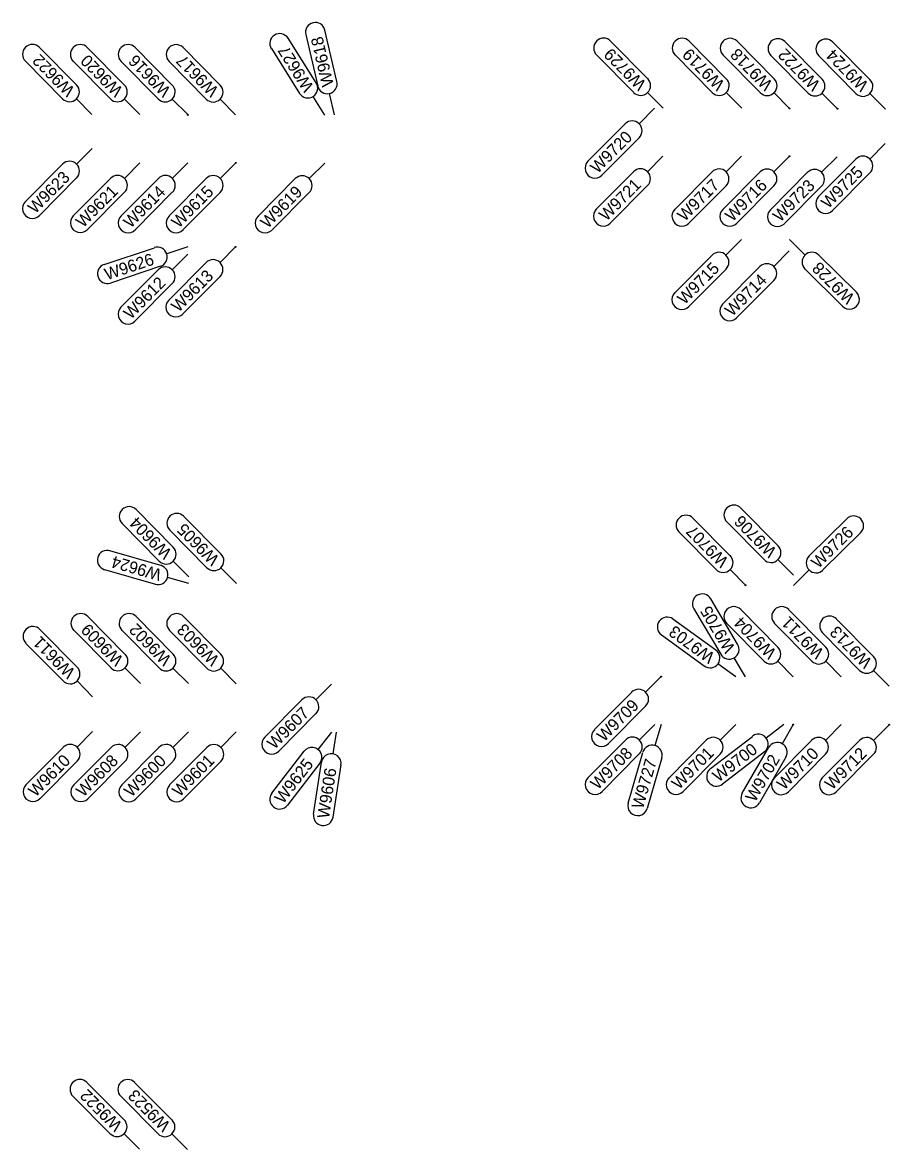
# Model space of a CAD drawing. Extents: x 12479652 to 12487250, y 9842710 to 9846560.
# Drawn here: x 12483660.6 to 12483751.2, y 9844494.3 to 9844612 of the extents above; entities that cross this region are included whole.
import ezdxf

# ---------------------------------------------------------------- set-up
doc = ezdxf.new("R2010")
doc.units = 0
doc.layers.add('Default', color=7, linetype='Continuous')
doc.layers.add('TextAlignmentLrg', color=7, linetype='Continuous')

msp = doc.modelspace()

# ---------------------------------------------------------------- linework, layer by layer
at = {"layer": 'Default'}
for p, q in [((12483690.21, 9844610.71), (12483691.46, 9844605.34)), ((12483693.46, 9844605.8), (12483692.21, 9844611.17)), ((12483691.3, 9844605.66), (12483688.36, 9844610.33)), ((12483725.91, 9844606.11), (12483722.04, 9844610.03)), ((12483734.12, 9844606.1), (12483730.24, 9844610.02)), ((12483739.12, 9844606.09), (12483735.24, 9844610.02)), ((12483744.12, 9844606.05), (12483740.24, 9844609.97)), ((12483749.12, 9844606.01), (12483745.24, 9844609.93)), ((12483666.28, 9844605.45), (12483662.4, 9844609.37)), ((12483671.28, 9844605.44), (12483667.4, 9844609.36)), ((12483676.28, 9844605.43), (12483672.4, 9844609.36)), ((12483681.28, 9844605.42), (12483677.4, 9844609.35)), ((12483686.62, 9844609.24), (12483689.56, 9844604.57)), ((12483720.58, 9844608.59), (12483724.45, 9844604.67)), ((12483728.78, 9844608.58), (12483732.66, 9844604.66)), ((12483733.78, 9844608.57), (12483737.66, 9844604.65)), ((12483738.78, 9844608.53), (12483742.66, 9844604.61)), ((12483743.78, 9844608.49), (12483747.66, 9844604.57)), ((12483660.94, 9844607.93), (12483664.82, 9844604.01)), ((12483665.94, 9844607.92), (12483669.82, 9844604)), ((12483670.94, 9844607.91), (12483674.82, 9844603.99)), ((12483675.94, 9844607.91), (12483679.82, 9844603.98)), ((12483667.89, 9844602.36), (12483666.27, 9844604)), ((12483672.89, 9844602.35), (12483671.27, 9844603.99)), ((12483677.89, 9844602.35), (12483676.27, 9844603.98)), ((12483682.89, 9844602.34), (12483681.27, 9844603.97)), ((12483692.2, 9844602.3), (12483690.97, 9844604.25)), ((12483693.22, 9844602.33), (12483692.7, 9844604.57)), ((12483727.52, 9844603.02), (12483725.91, 9844604.66)), ((12483735.73, 9844603.01), (12483734.11, 9844604.65)), ((12483740.73, 9844603), (12483739.11, 9844604.64)), ((12483745.73, 9844602.96), (12483744.11, 9844604.6)), ((12483750.73, 9844602.92), (12483749.11, 9844604.56)), ((12483726.63, 9844603.03), (12483725.01, 9844601.39)), ((12483719.67, 9844597.48), (12483723.56, 9844601.39)), ((12483725.02, 9844599.94), (12483721.13, 9844596.03)), ((12483750.72, 9844599.35), (12483749.1, 9844597.71)), ((12483667.9, 9844598.82), (12483666.28, 9844597.19)), ((12483727.51, 9844598.02), (12483725.89, 9844596.39)), ((12483735.72, 9844598.01), (12483734.1, 9844596.38)), ((12483740.72, 9844598), (12483739.1, 9844596.37)), ((12483743.76, 9844593.8), (12483747.65, 9844597.71)), ((12483745.69, 9844597.96), (12483744.06, 9844596.33)), ((12483660.94, 9844593.27), (12483664.83, 9844597.18)), ((12483672.9, 9844597.33), (12483671.28, 9844595.7)), ((12483677.9, 9844597.32), (12483676.28, 9844595.69)), ((12483682.9, 9844597.32), (12483681.28, 9844595.69)), ((12483692.19, 9844597.3), (12483690.57, 9844595.67)), ((12483666.29, 9844595.74), (12483662.4, 9844591.82)), ((12483665.94, 9844591.78), (12483669.83, 9844595.7)), ((12483670.94, 9844591.78), (12483674.83, 9844595.69)), ((12483675.94, 9844591.77), (12483679.83, 9844595.68)), ((12483685.23, 9844591.75), (12483689.12, 9844595.67)), ((12483720.55, 9844592.48), (12483724.44, 9844596.39)), ((12483728.76, 9844592.46), (12483732.65, 9844596.38)), ((12483733.76, 9844592.46), (12483737.65, 9844596.37)), ((12483738.72, 9844592.42), (12483742.61, 9844596.33)), ((12483749.1, 9844596.26), (12483745.21, 9844592.35)), ((12483671.28, 9844594.25), (12483667.39, 9844590.34)), ((12483676.28, 9844594.24), (12483672.39, 9844590.33)), ((12483681.28, 9844594.23), (12483677.39, 9844590.32)), ((12483690.58, 9844594.22), (12483686.69, 9844590.31)), ((12483725.9, 9844594.94), (12483722.01, 9844591.03)), ((12483734.1, 9844594.93), (12483730.21, 9844591.02)), ((12483739.1, 9844594.92), (12483735.21, 9844591.01)), ((12483744.07, 9844594.88), (12483740.18, 9844590.97)), ((12483669.18, 9844586.71), (12483674.41, 9844588.46)), ((12483677.89, 9844588.54), (12483675.71, 9844587.81)), ((12483682.89, 9844588.54), (12483681.27, 9844586.9)), ((12483735.71, 9844589.31), (12483734.08, 9844587.68)), ((12483740.71, 9844589.31), (12483742.34, 9844587.68)), ((12483677.89, 9844587.79), (12483676.27, 9844586.16)), ((12483728.74, 9844583.76), (12483732.63, 9844587.68)), ((12483740.7, 9844588.12), (12483739.08, 9844586.49)), ((12483743.79, 9844587.69), (12483747.7, 9844583.8)), ((12483675.06, 9844586.52), (12483669.83, 9844584.77)), ((12483670.92, 9844582.24), (12483674.81, 9844586.16)), ((12483675.93, 9844582.99), (12483679.82, 9844586.9)), ((12483734.09, 9844586.23), (12483730.2, 9844582.32)), ((12483733.74, 9844582.57), (12483737.63, 9844586.49)), ((12483746.25, 9844582.34), (12483742.34, 9844586.23)), ((12483681.27, 9844585.45), (12483677.38, 9844581.54)), ((12483739.09, 9844585.04), (12483735.2, 9844581.13)), ((12483676.27, 9844584.71), (12483672.38, 9844580.8)), ((12483739.52, 9844557.34), (12483735.64, 9844561.27)), ((12483676.38, 9844557.18), (12483672.5, 9844561.11)), ((12483681.36, 9844556.49), (12483677.48, 9844560.41)), ((12483734.52, 9844556.3), (12483730.64, 9844560.22)), ((12483746.7, 9844560.15), (12483742.77, 9844556.27)), ((12483671.04, 9844559.67), (12483674.92, 9844555.74)), ((12483676.02, 9844558.97), (12483679.9, 9844555.04)), ((12483734.18, 9844559.83), (12483738.06, 9844555.9)), ((12483729.18, 9844558.78), (12483733.06, 9844554.86)), ((12483744.21, 9844554.81), (12483748.14, 9844558.69)), ((12483675.07, 9844555.29), (12483669.77, 9844556.82)), ((12483677.99, 9844554.1), (12483676.37, 9844555.73)), ((12483741.13, 9844554.26), (12483739.51, 9844555.89)), ((12483669.21, 9844554.85), (12483674.51, 9844553.32)), ((12483682.97, 9844553.4), (12483681.35, 9844555.04)), ((12483736.13, 9844553.21), (12483734.51, 9844554.85)), ((12483741.13, 9844553.2), (12483742.76, 9844554.82)), ((12483677.99, 9844553.39), (12483675.78, 9844554.02)), ((12483735.3, 9844547.06), (12483732.5, 9844551.81)), ((12483730.73, 9844550.76), (12483733.54, 9844546.01)), ((12483739.51, 9844546.75), (12483735.63, 9844550.67)), ((12483744.51, 9844546.74), (12483740.63, 9844550.67)), ((12483671.34, 9844546.03), (12483667.46, 9844549.95)), ((12483676.36, 9844546.02), (12483672.49, 9844549.95)), ((12483681.34, 9844546.01), (12483677.46, 9844549.94)), ((12483733.02, 9844546.45), (12483728.55, 9844549.69)), ((12483749.5, 9844545.77), (12483745.63, 9844549.69)), ((12483666.34, 9844544.67), (12483662.46, 9844548.6)), ((12483666, 9844548.51), (12483669.88, 9844544.59)), ((12483671.03, 9844548.5), (12483674.9, 9844544.58)), ((12483676, 9844548.5), (12483679.88, 9844544.57)), ((12483734.17, 9844549.23), (12483738.05, 9844545.31)), ((12483739.17, 9844549.22), (12483743.05, 9844545.3)), ((12483661, 9844547.15), (12483664.88, 9844543.23)), ((12483727.35, 9844548.03), (12483731.82, 9844544.79)), ((12483744.17, 9844548.25), (12483748.04, 9844544.33)), ((12483735.11, 9844543.67), (12483733.25, 9844545.02)), ((12483736.11, 9844543.67), (12483734.94, 9844545.65)), ((12483741.11, 9844543.66), (12483739.5, 9844545.3)), ((12483746.11, 9844543.66), (12483744.5, 9844545.29)), ((12483672.95, 9844542.94), (12483671.33, 9844544.58)), ((12483677.97, 9844542.94), (12483676.35, 9844544.57)), ((12483682.95, 9844542.93), (12483681.33, 9844544.56)), ((12483727.32, 9844543.68), (12483725.7, 9844542.05)), ((12483751.11, 9844542.68), (12483749.49, 9844544.32)), ((12483667.95, 9844541.58), (12483666.33, 9844543.22)), ((12483692.9, 9844542.89), (12483691.27, 9844541.26)), ((12483685.93, 9844537.34), (12483689.82, 9844541.26)), ((12483720.36, 9844538.14), (12483724.25, 9844542.05)), ((12483725.7, 9844540.6), (12483721.81, 9844536.69)), ((12483691.28, 9844539.81), (12483687.39, 9844535.9)), ((12483667.96, 9844537.93), (12483666.34, 9844536.3)), ((12483672.96, 9844537.92), (12483671.34, 9844536.29)), ((12483677.96, 9844537.91), (12483676.34, 9844536.28)), ((12483682.96, 9844537.91), (12483681.34, 9844536.28)), ((12483692.89, 9844537.89), (12483691.48, 9844536.07)), ((12483693.38, 9844537.89), (12483693.03, 9844535.62)), ((12483726.65, 9844538.68), (12483725.03, 9844537.05)), ((12483727.31, 9844538.68), (12483726.67, 9844536.47)), ((12483735.11, 9844538.67), (12483733.48, 9844537.04)), ((12483740.11, 9844538.66), (12483738.28, 9844537.26)), ((12483741.11, 9844538.66), (12483739.95, 9844536.67)), ((12483746.11, 9844538.66), (12483744.48, 9844537.02)), ((12483751.11, 9844538.65), (12483749.48, 9844537.02)), ((12483719.69, 9844533.14), (12483723.58, 9844537.05)), ((12483728.14, 9844533.12), (12483732.03, 9844537.04)), ((12483732.48, 9844534.07), (12483736.85, 9844537.44)), ((12483739.14, 9844533.11), (12483743.03, 9844537.02)), ((12483744.14, 9844533.1), (12483748.03, 9844537.01)), ((12483661, 9844532.38), (12483664.89, 9844536.29)), ((12483666, 9844532.37), (12483669.89, 9844536.29)), ((12483671, 9844532.37), (12483674.89, 9844536.28)), ((12483676, 9844532.36), (12483679.89, 9844536.27)), ((12483686.68, 9844531.51), (12483690.05, 9844535.88)), ((12483725.04, 9844535.6), (12483721.15, 9844531.69)), ((12483723.88, 9844530.47), (12483725.4, 9844535.77)), ((12483733.49, 9844535.59), (12483729.6, 9844531.68)), ((12483738.1, 9844535.82), (12483733.73, 9844532.45)), ((12483735.79, 9844531.52), (12483738.55, 9844536.3)), ((12483744.49, 9844535.57), (12483740.6, 9844531.66)), ((12483749.49, 9844535.57), (12483745.6, 9844531.65)), ((12483666.35, 9844534.85), (12483662.46, 9844530.93)), ((12483671.35, 9844534.84), (12483667.46, 9844530.93)), ((12483676.35, 9844534.83), (12483672.46, 9844530.92)), ((12483681.35, 9844534.82), (12483677.46, 9844530.91)), ((12483691.67, 9844534.63), (12483688.31, 9844530.26)), ((12483691.02, 9844529.31), (12483691.86, 9844534.76)), ((12483693.89, 9844534.45), (12483693.05, 9844528.99)), ((12483727.38, 9844535.2), (12483725.85, 9844529.9)), ((12483740.33, 9844535.27), (12483737.57, 9844530.49)), ((12483671.24, 9844497.4), (12483667.35, 9844501.31)), ((12483676.24, 9844497.39), (12483672.35, 9844501.3)), ((12483665.9, 9844499.87), (12483669.79, 9844495.95)), ((12483670.9, 9844499.86), (12483674.79, 9844495.94)), ((12483672.86, 9844494.32), (12483671.24, 9844495.95)), ((12483677.86, 9844494.31), (12483676.24, 9844495.94))]:
    msp.add_line(p, q, dxfattribs=at)
for centre, start, end in [((12483691.21, 9844610.94), 13.1464, 193.1464), ((12483687.49, 9844609.78), 32.2035, 212.2035), ((12483661.67, 9844608.65), 44.6553, 224.6553), ((12483666.67, 9844608.64), 44.6553, 224.6553), ((12483671.67, 9844608.64), 44.6553, 224.6553), ((12483676.67, 9844608.63), 44.6553, 224.6553), ((12483721.31, 9844609.31), 44.6553, 224.6553), ((12483729.51, 9844609.3), 44.6553, 224.6553), ((12483734.51, 9844609.29), 44.6553, 224.6553), ((12483739.51, 9844609.25), 44.6553, 224.6553), ((12483744.51, 9844609.21), 44.6553, 224.6553), ((12483725.18, 9844605.39), 224.6553, 44.6553), ((12483733.39, 9844605.38), 224.6553, 44.6553), ((12483738.39, 9844605.37), 224.6553, 44.6553), ((12483743.39, 9844605.33), 224.6553, 44.6553), ((12483748.39, 9844605.29), 224.6553, 44.6553), ((12483665.55, 9844604.73), 224.6553, 44.6553), ((12483670.55, 9844604.72), 224.6553, 44.6553), ((12483675.55, 9844604.71), 224.6553, 44.6553), ((12483680.55, 9844604.7), 224.6553, 44.6553), ((12483690.43, 9844605.12), 212.2035, 32.2035), ((12483692.46, 9844605.57), 193.1464, 13.1464), ((12483724.29, 9844600.67), 315.1702, 135.1702), ((12483748.38, 9844596.99), 315.1702, 135.1702), ((12483665.56, 9844596.46), 315.1702, 135.1702), ((12483720.4, 9844596.75), 135.1702, 315.1702), ((12483725.17, 9844595.67), 315.1702, 135.1702), ((12483733.37, 9844595.65), 315.1702, 135.1702), ((12483738.37, 9844595.64), 315.1702, 135.1702), ((12483743.34, 9844595.6), 315.1702, 135.1702), ((12483670.56, 9844594.97), 315.1702, 135.1702), ((12483675.56, 9844594.97), 315.1702, 135.1702), ((12483680.56, 9844594.96), 315.1702, 135.1702), ((12483689.85, 9844594.94), 315.1702, 135.1702), ((12483661.67, 9844592.55), 135.1702, 315.1702), ((12483744.49, 9844593.07), 135.1702, 315.1702), ((12483721.28, 9844591.75), 135.1702, 315.1702), ((12483729.48, 9844591.74), 135.1702, 315.1702), ((12483734.48, 9844591.73), 135.1702, 315.1702), ((12483739.45, 9844591.69), 135.1702, 315.1702), ((12483666.67, 9844591.06), 135.1702, 315.1702), ((12483671.67, 9844591.05), 135.1702, 315.1702), ((12483676.67, 9844591.04), 135.1702, 315.1702), ((12483685.96, 9844591.03), 135.1702, 315.1702), ((12483674.73, 9844587.49), 288.4892, 108.4892), ((12483680.54, 9844586.18), 315.1702, 135.1702), ((12483733.36, 9844586.95), 315.1702, 135.1702), ((12483743.06, 9844586.96), 45.1702, 225.1702), ((12483669.5, 9844585.74), 108.4892, 288.4892), ((12483675.54, 9844585.43), 315.1702, 135.1702), ((12483738.36, 9844585.76), 315.1702, 135.1702), ((12483729.47, 9844583.04), 135.1702, 315.1702), ((12483746.98, 9844583.07), 225.1702, 45.1702), ((12483676.65, 9844582.26), 135.1702, 315.1702), ((12483734.47, 9844581.85), 135.1702, 315.1702), ((12483671.65, 9844581.52), 135.1702, 315.1702), ((12483671.77, 9844560.39), 44.6553, 224.6553), ((12483734.91, 9844560.55), 44.6553, 224.6553), ((12483676.75, 9844559.69), 44.6553, 224.6553), ((12483729.91, 9844559.5), 44.6553, 224.6553), ((12483747.42, 9844559.42), 314.6553, 134.6553), ((12483669.49, 9844555.83), 73.9221, 253.9221), ((12483675.65, 9844556.46), 224.6553, 44.6553), ((12483738.79, 9844556.62), 224.6553, 44.6553), ((12483680.63, 9844555.77), 224.6553, 44.6553), ((12483733.79, 9844555.58), 224.6553, 44.6553), ((12483743.49, 9844555.54), 134.6553, 314.6553), ((12483674.79, 9844554.31), 253.9221, 73.9221), ((12483731.61, 9844551.28), 30.5813, 210.5813), ((12483734.9, 9844549.95), 44.6553, 224.6553), ((12483739.9, 9844549.95), 44.6553, 224.6553), ((12483666.73, 9844549.23), 44.6553, 224.6553), ((12483671.76, 9844549.23), 44.6553, 224.6553), ((12483676.73, 9844549.22), 44.6553, 224.6553), ((12483727.95, 9844548.86), 54.1073, 234.1073), ((12483744.9, 9844548.97), 44.6553, 224.6553), ((12483661.73, 9844547.88), 44.6553, 224.6553), ((12483670.61, 9844545.31), 224.6553, 44.6553), ((12483675.63, 9844545.3), 224.6553, 44.6553), ((12483680.61, 9844545.29), 224.6553, 44.6553), ((12483732.42, 9844545.62), 234.1073, 54.1073), ((12483734.42, 9844546.53), 210.5813, 30.5813), ((12483738.78, 9844546.03), 224.6553, 44.6553), ((12483743.78, 9844546.02), 224.6553, 44.6553), ((12483748.77, 9844545.05), 224.6553, 44.6553), ((12483665.61, 9844543.95), 224.6553, 44.6553), ((12483690.55, 9844540.53), 315.1702, 135.1702), ((12483724.97, 9844541.32), 315.1702, 135.1702), ((12483721.09, 9844537.41), 135.1702, 315.1702), ((12483665.62, 9844535.57), 315.1702, 135.1702), ((12483670.62, 9844535.56), 315.1702, 135.1702), ((12483675.62, 9844535.56), 315.1702, 135.1702), ((12483680.62, 9844535.55), 315.1702, 135.1702), ((12483686.66, 9844536.62), 135.1702, 315.1702), ((12483724.31, 9844536.33), 315.1702, 135.1702), ((12483726.39, 9844535.49), 343.9089, 163.9089), ((12483732.76, 9844536.31), 315.1702, 135.1702), ((12483737.47, 9844536.63), 307.657, 127.657), ((12483739.44, 9844535.78), 329.9638, 149.9638), ((12483743.76, 9844536.3), 315.1702, 135.1702), ((12483748.76, 9844536.29), 315.1702, 135.1702), ((12483690.86, 9844535.26), 322.4034, 142.4035), ((12483692.87, 9844534.6), 351.2732, 171.2732), ((12483720.42, 9844532.41), 135.1702, 315.1702), ((12483728.87, 9844532.4), 135.1702, 315.1702), ((12483733.1, 9844533.26), 127.657, 307.657), ((12483739.87, 9844532.38), 135.1702, 315.1702), ((12483744.87, 9844532.38), 135.1702, 315.1702), ((12483661.73, 9844531.66), 135.1702, 315.1702), ((12483666.73, 9844531.65), 135.1702, 315.1702), ((12483671.73, 9844531.64), 135.1702, 315.1702), ((12483676.73, 9844531.63), 135.1702, 315.1702), ((12483687.49, 9844530.88), 142.4035, 322.4034), ((12483736.68, 9844531.01), 149.9638, 329.9638), ((12483724.86, 9844530.19), 163.9089, 343.9089), ((12483692.04, 9844529.15), 171.2732, 351.2732), ((12483666.63, 9844500.59), 44.8253, 224.8253), ((12483671.63, 9844500.58), 44.8253, 224.8253), ((12483670.52, 9844496.68), 224.8253, 44.8253), ((12483675.52, 9844496.67), 224.8253, 44.8253)]:
    msp.add_arc(centre, 1.03, start, end, dxfattribs=at)
at = {"layer": 'TextAlignmentLrg'}
for centre in [(12483740.73, 9844603), (12483745.73, 9844602.96), (12483677.91, 9844602.32), (12483740.72, 9844598), (12483682.9, 9844597.32), (12483682.89, 9844588.54), (12483736.13, 9844553.21), (12483727.32, 9844543.68), (12483741.11, 9844538.66), (12483751.11, 9844538.65)]:
    msp.add_circle(centre, 0.05, dxfattribs=at)

# ---------------------------------------------------------------- texts
at = {"layer": 'Default'}
for s, rotation, p in [('W9618', 103.1464, (12483693.15, 9844605.44)), ('W9622', 134.6553, (12483666.18, 9844604.99)), ('W9620', 134.6553, (12483671.2, 9844604.96)), ('W9616', 134.6553, (12483676.2, 9844604.95)), ('W9617', 134.6553, (12483681.19, 9844604.96)), ('W9627', 122.2035, (12483691.11, 9844605.23)), ('W9729', 134.6553, (12483725.84, 9844605.63)), ('W9719', 134.6553, (12483734.04, 9844605.62)), ('W9718', 134.6553, (12483739.04, 9844605.61)), ('W9722', 134.6553, (12483744.02, 9844605.59)), ('W9724', 134.6553, (12483749.05, 9844605.53)), ('W9720', 45.1702, (12483720.67, 9844596.13)), ('W9725', 45.1702, (12483744.77, 9844592.46)), ('W9623', 45.1702, (12483661.95, 9844591.93)), ('W9721', 45.1702, (12483721.59, 9844591.16)), ('W9717', 45.1702, (12483729.77, 9844591.12)), ('W9716', 45.1702, (12483734.75, 9844591.1)), ('W9723', 45.1702, (12483739.73, 9844591.07)), ('W9621', 45.1702, (12483666.97, 9844590.47)), ('W9614', 45.1702, (12483671.93, 9844590.42)), ('W9615', 45.1702, (12483676.95, 9844590.43)), ('W9619', 45.1702, (12483686.23, 9844590.4)), ('W9626', 18.4892, (12483669.46, 9844585.05)), ('W9613', 45.1702, (12483676.93, 9844581.64)), ('W9715', 45.1702, (12483729.76, 9844582.43)), ('W9728', 135.1702, (12483747.6, 9844583.34)), ('W9612', 45.1702, (12483671.94, 9844580.91)), ('W9714', 45.1702, (12483734.73, 9844581.21)), ('W9604', 134.6553, (12483676.31, 9844556.7)), ('W9706', 134.6553, (12483739.45, 9844556.86)), ('W9605', 134.6553, (12483681.27, 9844556.02)), ('W9707', 134.6553, (12483734.43, 9844555.83)), ('W9726', 44.6553, (12483743.73, 9844554.89)), ('W9624', 163.9221, (12483675.25, 9844554.84)), ('W9705', 120.5813, (12483735.1, 9844546.63)), ('W9704', 134.6553, (12483739.43, 9844546.27)), ('W9711', 134.6553, (12483744.39, 9844546.3)), ('W9609', 134.6553, (12483671.26, 9844545.55)), ('W9602', 134.6553, (12483676.27, 9844545.57)), ('W9603', 134.6553, (12483681.26, 9844545.55)), ('W9703', 144.1073, (12483733.01, 9844545.98)), ('W9713', 134.6553, (12483749.42, 9844545.3)), ('W9611', 134.6553, (12483666.23, 9844544.23)), ('W9709', 45.1702, (12483721.36, 9844536.79)), ('W9607', 45.1702, (12483686.94, 9844536)), ('W9700', 37.657, (12483733.29, 9844532.6)), ('W9610', 45.1702, (12483662, 9844531.03)), ('W9608', 45.1702, (12483667, 9844531.02)), ('W9600', 45.1702, (12483672, 9844531.01)), ('W9601', 45.1702, (12483677.04, 9844531.04)), ('W9708', 45.1702, (12483720.69, 9844531.79)), ('W9701', 45.1702, (12483729.18, 9844531.81)), ('W9702', 59.9638, (12483737.12, 9844530.49)), ('W9710', 45.1702, (12483740.14, 9844531.76)), ('W9712', 45.1702, (12483745.16, 9844531.77)), ('W9625', 52.4034, (12483687.85, 9844530.31)), ('W9727', 73.9089, (12483725.41, 9844529.78)), ('W9606', 81.2732, (12483692.63, 9844528.8)), ('W9522', 134.8253, (12483671.15, 9844496.94)), ('W9523', 134.8253, (12483676.16, 9844496.92))]:
    msp.add_text(s, height=1.25, rotation=rotation, dxfattribs=at).set_placement(p)

doc.saveas('drawing.dxf')
